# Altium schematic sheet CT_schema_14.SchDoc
size 500 x 385 mm
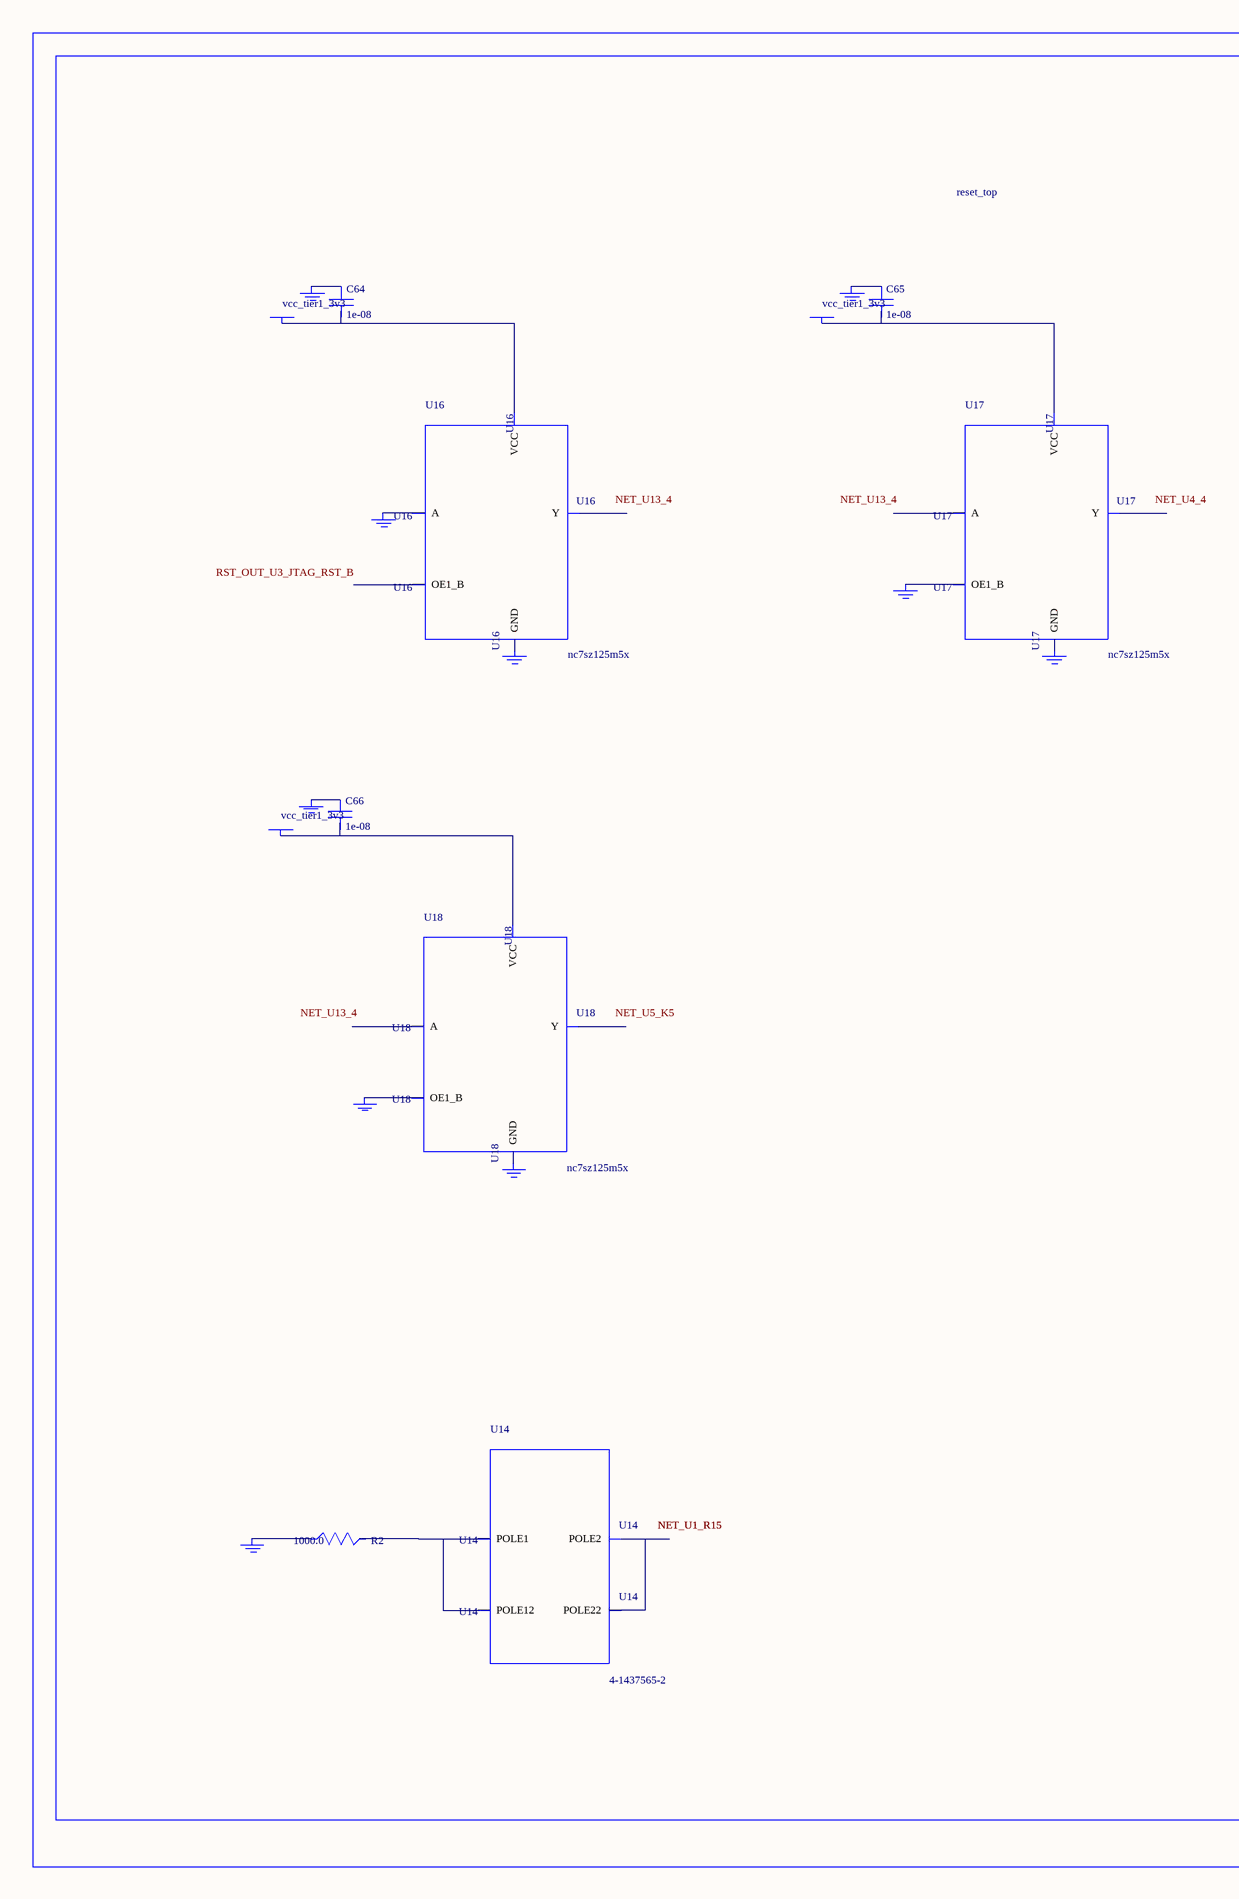
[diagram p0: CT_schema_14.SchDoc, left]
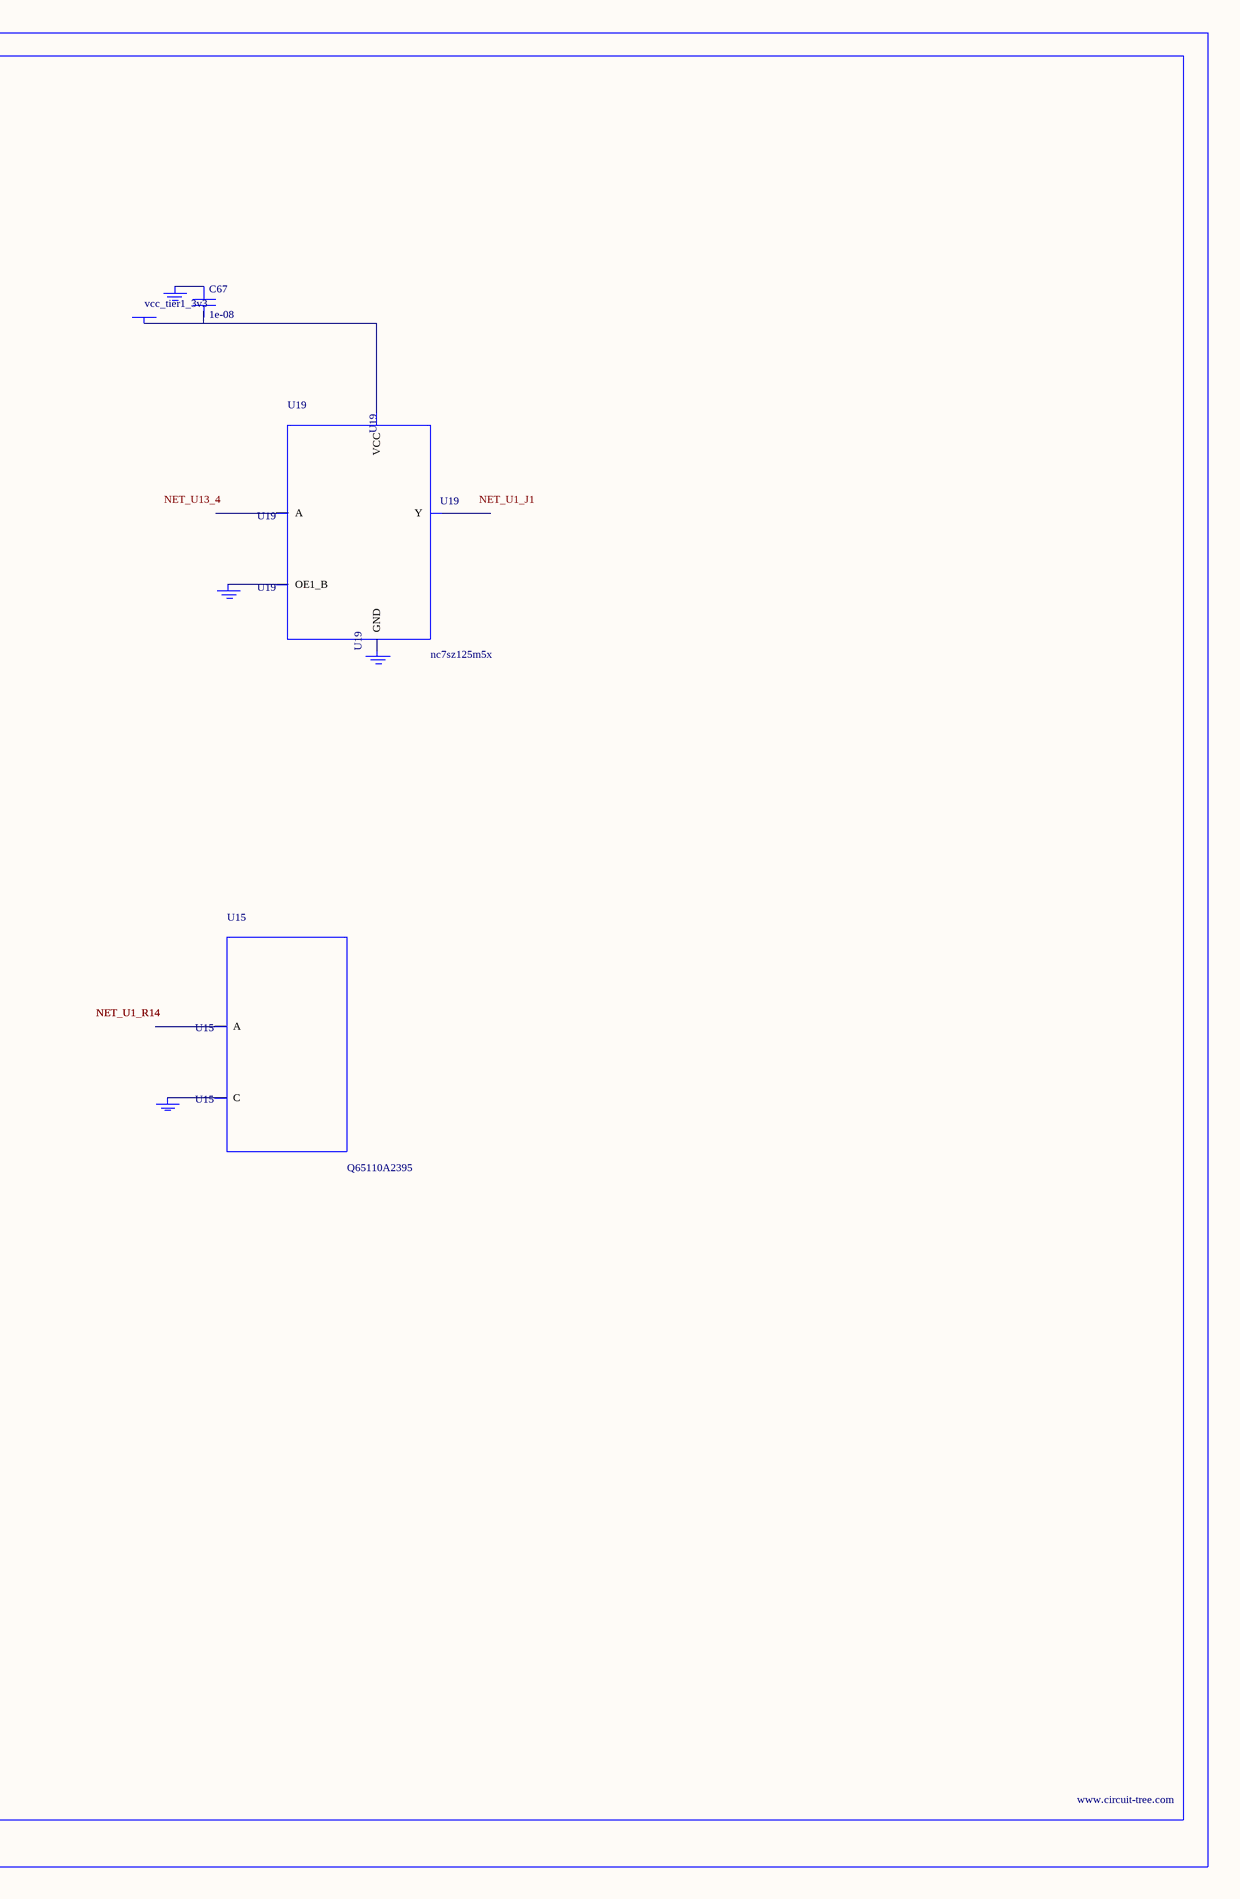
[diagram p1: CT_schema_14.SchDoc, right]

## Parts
BORDER13  (no value)
C64  1e-08  [C0402]
C65  1e-08  [C0402]
C66  1e-08  [C0402]
C67  1e-08  [C0402]
GND_INSTANCE_13_0  (no value)
GND_INSTANCE_13_1  (no value)
GND_INSTANCE_13_2  (no value)
GND_INSTANCE_13_3  (no value)
GND_INSTANCE_13_4  (no value)
GND_INSTANCE_13_5  (no value)
GND_INSTANCE_13_6  (no value)
GND_INSTANCE_13_7  (no value)
GND_INSTANCE_13_8  (no value)
GND_INSTANCE_13_9  (no value)
GND_INSTANCE_13_10  (no value)
GND_INSTANCE_13_11  (no value)
GND_INSTANCE_13_12  (no value)
GND_INSTANCE_13_13  (no value)
POWER_INSTANCE_13_0  vcc_tier1_3v3
POWER_INSTANCE_13_1  vcc_tier1_3v3
POWER_INSTANCE_13_2  vcc_tier1_3v3
POWER_INSTANCE_13_3  vcc_tier1_3v3
R2  1000.0  [R0603]
U14  4-1437565-2  [SW_4-1437565-2]
U15  Q65110A2395  [LGM67K-G1J2-24-Z]
U16  nc7sz125m5x  [NC7SZ125M5X]
U17  nc7sz125m5x  [NC7SZ125M5X]
U18  nc7sz125m5x  [NC7SZ125M5X]
U19  nc7sz125m5x  [NC7SZ125M5X]

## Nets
NetC64_1: C64.1 GND_INSTANCE_13_2.0(GND)
NetC64_2: C64.2 POWER_INSTANCE_13_0.0(PWR) U16.5(VCC)
NetC65_1: C65.1 GND_INSTANCE_13_5.0(GND)
NetC65_2: C65.2 POWER_INSTANCE_13_1.0(PWR) U17.5(VCC)
NetC66_1: C66.1 GND_INSTANCE_13_8.0(GND)
NetC66_2: C66.2 POWER_INSTANCE_13_2.0(PWR) U18.5(VCC)
NetC67_1: C67.1 GND_INSTANCE_13_11.0(GND)
NetC67_2: C67.2 POWER_INSTANCE_13_3.0(PWR) U19.5(VCC)
NetGND_INSTANCE_13_0_0: GND_INSTANCE_13_0.0(GND) R2.1
NetGND_INSTANCE_13_1_0: GND_INSTANCE_13_1.0(GND) U15.C
NetGND_INSTANCE_13_3_0: GND_INSTANCE_13_3.0(GND) U16.2(A)
NetGND_INSTANCE_13_4_0: GND_INSTANCE_13_4.0(GND) U16.3(GND)
NetGND_INSTANCE_13_6_0: GND_INSTANCE_13_6.0(GND) U17.1(OE1_B)
NetGND_INSTANCE_13_7_0: GND_INSTANCE_13_7.0(GND) U17.3(GND)
NetGND_INSTANCE_13_9_0: GND_INSTANCE_13_9.0(GND) U18.1(OE1_B)
NetGND_INSTANCE_13_10_0: GND_INSTANCE_13_10.0(GND) U18.3(GND)
NetGND_INSTANCE_13_12_0: GND_INSTANCE_13_12.0(GND) U19.1(OE1_B)
NetGND_INSTANCE_13_13_0: GND_INSTANCE_13_13.0(GND) U19.3(GND)
NetR2_2: R2.2 U14.1(POLE1) U14.2(POLE12)
NetU14_3: U14.3(POLE2) U14.4(POLE22)

Not connected (* = marked no-connect by the designer): U15 A; U16 1(OE1_B) 4(Y); U17 2(A) 4(Y); U18 2(A) 4(Y); U19 2(A) 4(Y)

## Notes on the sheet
- Labels drawn without touching a wire or pin: NET_U1_J1, NET_U4_4, NET_U5_K5, NET_U13_4, RST_OUT_U3_JTAG_RST_B

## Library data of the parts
BORDER13 = BORDER_PAGE13
C64-C67 = C0402C103K3RAC
GND_INSTANCE_13_0-GND_INSTANCE_13_13 = GND
POWER_INSTANCE_13_0-POWER_INSTANCE_13_3 = PWR
R2 = RC0603JR-071KL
